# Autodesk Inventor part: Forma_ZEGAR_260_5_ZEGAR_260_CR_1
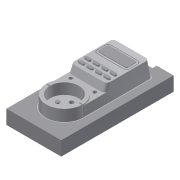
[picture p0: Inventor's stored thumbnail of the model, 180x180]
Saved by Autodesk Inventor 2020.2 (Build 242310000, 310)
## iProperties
Created: 2015-01
Part Number: Forma_ZEGAR_260_5_ZEGAR_260_CR_1
Material: Ogólny
Document SubType Name: Modeling
Designer: F.Stasiak
Density: 1 g/cm^3
Appearance: Domyślna
Catalog Web Link: www.expertbooks.pl
Manager: www.cadconsulting.pl
Company: Fabian Stasiak CAD Consulting
Author: F.Stasiak
Subject: Zbiór ćwiczeń. Autodesk Inventor 2020. Kurs Professional
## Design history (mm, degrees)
node "Forma_ZEGAR_260_4_ZEGAR_260_CR_Base"
feature "Bryła1::Forma_ZEGAR_260_4_ZEGAR_260_CR_Base"
tag "Bryła wyprowadzona1"
node "Bryła1"
feature "Forma_ZEGAR_260_4_ZEGAR_260_CR_Base_Bodies"
